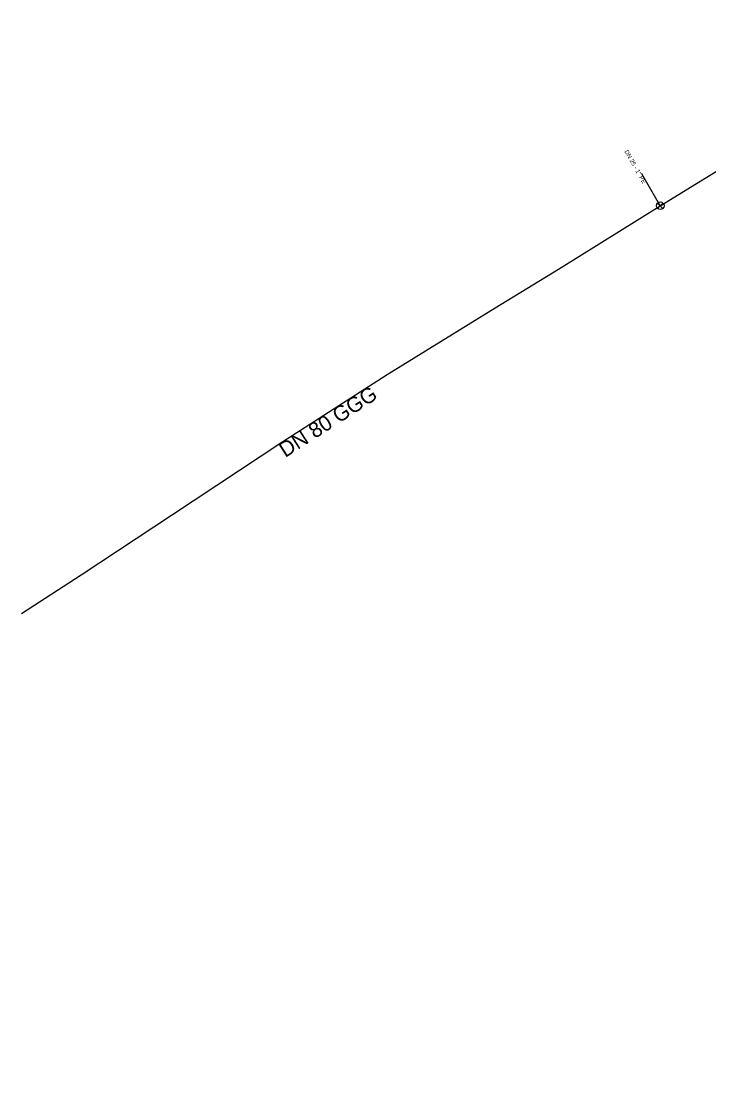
# Model space of a CAD drawing. Extents: x -492321 to -492053, y -1126159 to -1125902.
# Drawn here: x -492320.6 to -492248.3, y -1126159.4 to -1126047.1 of the extents above; entities that cross this region are included whole.
import ezdxf

# ---------------------------------------------------------------- set-up
doc = ezdxf.new("R2010")
doc.units = 0
for name, color, linetype in [('_pripojka_prevzato_z_dokumentace_', 7, 'Continuous'), ('_pripojka_priblizne_', 7, 'Continuous'), ('_voda_smvak_prevzato_z_dokumentace_', 7, 'Continuous'), ('Default', 7, 'Continuous'), ('MoLevel 32', 7, 'Continuous'), ('MoLevel 46', 7, 'Continuous'), ('MoLevel 53', 7, 'Continuous')]:
    doc.layers.add(name, color=color, linetype=linetype)

# ---------------------------------------------------------------- blocks, each defined once
blk = doc.blocks.new('_uzaver_pripojka_')
at = {"layer": 'Default'}
for p, q in [((-0.000035, -0.000035), (0.000035, 0.000035)), ((0.000035, -0.000035), (-0.000035, 0.000035))]:
    blk.add_line(p, q, dxfattribs=at)
for radius in [0.00005, 0.0000025]:
    blk.add_circle((0, 0), radius, dxfattribs=at)

msp = doc.modelspace()

# ---------------------------------------------------------------- linework, layer by layer
at = {"layer": '_pripojka_prevzato_z_dokumentace_'}
msp.add_line((-492253.41, -1126066.5), (-492253.75, -1126065.95), dxfattribs=at)
at = {"layer": '_pripojka_priblizne_'}
msp.add_line((-492253.75, -1126065.95), (-492255.35, -1126063.14), dxfattribs=at)
at = {"layer": '_voda_smvak_prevzato_z_dokumentace_'}
msp.add_lwpolyline([(-492320.55, -1126109.34), (-492314.27, -1126105.27), (-492304.68, -1126098.93), (-492293.08, -1126091.26), (-492282.11, -1126084.21), (-492270.76, -1126077.22), (-492264.09, -1126073.17), (-492253.41, -1126066.5), (-492241.96, -1126059.49), (-492233.97, -1126054.69), (-492222.62, -1126048.03), (-492221.11, -1126047.14), (-492220.43, -1126048.46), (-492198.94, -1126095.74), (-492189.88, -1126116.75), (-492173.99, -1126152.32), (-492170.78, -1126159.44)], dxfattribs=at)

# ---------------------------------------------------------------- block references
at = {"layer": 'MoLevel 53', "xscale": 7999.999999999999, "yscale": 7999.999999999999}
msp.add_blockref('_uzaver_pripojka_', (-492253.41, -1126066.5), dxfattribs=at)

# ---------------------------------------------------------------- texts
at = {"layer": 'MoLevel 32'}
msp.add_text("DN 25 - 1'' PE", height=0.455, rotation=299.5845, dxfattribs=at).set_placement((-492257.19, -1126060.81))
at = {"layer": 'MoLevel 46'}
msp.add_text('DN 80 GGG', height=1.605, rotation=32.7273, dxfattribs=at).set_placement((-492292.82, -1126093))

doc.saveas('drawing.dxf')
